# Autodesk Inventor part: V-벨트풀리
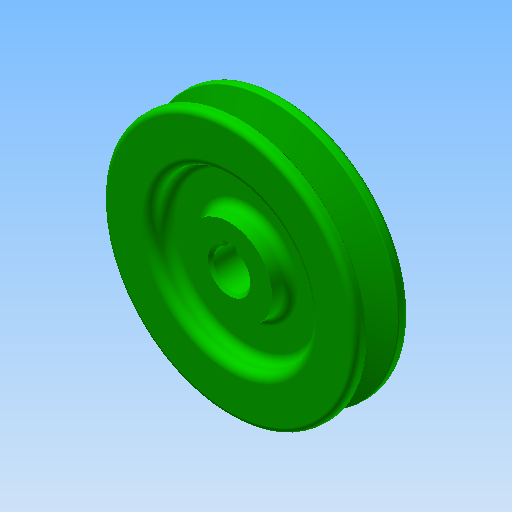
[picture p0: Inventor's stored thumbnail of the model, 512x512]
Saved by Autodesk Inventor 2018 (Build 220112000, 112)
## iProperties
Created: 2024-02
Part Number: V-벨트풀리
Material: 주철, 주조
Document SubType Name: Modeling
Designer: mdu-01
Density: 1 g/cm^3
Appearance: 기본값(1)
Author: mdu-01
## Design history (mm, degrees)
sketch "스케치1"
  geometry: L1 (0, 10)-(0, -10); L2 (0, 0)-(35, 0); L3 (0, 10)-(16, 10); L4 (16, 10)-(16, 6); L5 (19, 3)-(27, 3); L6 (30, 6)-(30, 7); L7 (33, 10)-(45.5, 10); L8 (47.5, 8)-(47.5, 6.346); L9 (47.146, 5.868)-(35.708, 2.37); L10 (0, -10)-(16, -10); L11 (16, -10)-(16, -6); L12 (19, -3)-(27, -3); L13 (30, -6)-(30, -7); L14 (33, -10)-(45.5, -10); L15 (47.5, -8)-(47.5, -6.346); L16 (47.146, -5.868)-(35.708, -2.37); L17 (35, 1.414)-(35, -1.414); L18 (7, 9)-(7, -9); L19 (9.3, 10)-(9.3, -10); L20 (-7, 10)-(-7, -10); L21 (7, 9)-(8, 10); L22 (7, -9)-(8, -10); A1 r 0.5 centre (47, 6.346) between (47.146, 5.868) and (47.5, 6.346); A2 r 0.5 centre (47, -6.346) between (47.5, -6.346) and (47.146, -5.868); A3 r 1 centre (36, 1.414) between (35.708, 2.37) and (35, 1.414); A4 r 1 centre (36, -1.414) between (35, -1.414) and (35.708, -2.37); A5 r 2 centre (45.5, 8) between (47.5, 8) and (45.5, 10); A6 r 2 centre (45.5, -8) between (45.5, -10) and (47.5, -8); A7 r 3 centre (33, 7) between (33, 10) and (30, 7); A8 r 3 centre (27, 6) between (27, 3) and (30, 6); A9 r 3 centre (27, -6) between (30, -6) and (27, -3); A10 r 3 centre (33, -7) between (30, -7) and (33, -10); A11 r 3 centre (19, -6) between (19, -3) and (16, -6); A12 r 3 centre (19, 6) between (16, 6) and (19, 3); 18 further points
  constraints: 44 end point, 35 point on line, 24 point on circle, 24 tangent, 12 centre point, 10 symmetric about line, 8 equal radius, 6 parallel, 4 midpoint, 3 perpendicular, 2 collinear, 1 coincident, 1 vertical
  dimensions: "d0" = 20 distance of L1.start L1.end; "d2" = 86 diameter of point (43, 4.6) L1; "d3" = 9.2 diameter of point (43, 4.6) L2; "d4" = 34 deg angle of L16 L9; "d5" = 4.5 distance from line of L8 point (43, 4.6); "d6" = 8 distance from line of L17 point (43, 4.6); "d7" = 14 diameter of L18 L1; "d8" = 16.3 distance between parallel lines of L19 L20; "d9" = 32 diameter of L11 L1; "d10" = 60 diameter of L13 L1; "d11" = 6 distance between parallel lines of L12 L5; "d12" = 0.5 radius of A1; "d13" = 1 radius of A3; "d14" = 2 radius of A5; "d15" = 1 distance of L18.start point (7, 10); "d17" = 1 distance of L18.end point (7, -10) (= d15); "d19" = 45 deg angle of L22 L18; "d20" = 45 deg angle of L21 L18; "d21" = 3 radius of A7
revolve "회전1" stored, may be unused: angle "d22" = 90 deg
extrude "돌출1" cut sketch "스케치1" stored distance "d23" = 5; taper "d24" = 0 deg
node "솔리드1"
